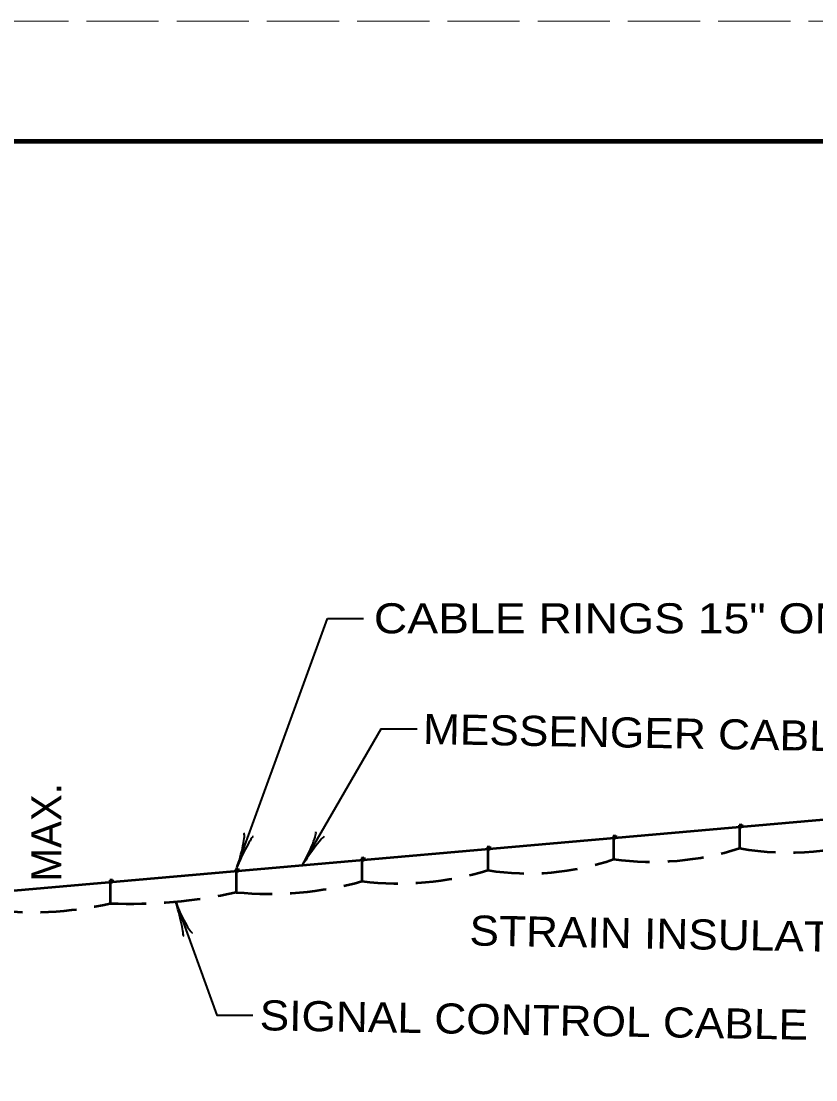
# Model space of a CAD drawing. Extents: x 12366 to 13046, y 9129 to 9570.
# Drawn here: x 12563.1 to 12629.1, y 9481.6 to 9569.5 of the extents above; entities that cross this region are included whole.
import ezdxf
from ezdxf.enums import TextEntityAlignment as Align

# ---------------------------------------------------------------- set-up
doc = ezdxf.new("R2010")
doc.units = 0
doc.linetypes.add('LONG_DASHED', pattern=[7.5, 6, -1.5])
doc.linetypes.add('MEDIUM_DASHED', pattern=[4.5, 3, -1.5])
doc.layers.add('1', color=7, linetype='Continuous', lineweight=53)
doc.layers.add('61', color=7, linetype='Continuous', lineweight=35)

msp = doc.modelspace()

# ---------------------------------------------------------------- linework, layer by layer
at = {"layer": '1', "lineweight": 35}
for p, q in [((12580.994, 9499.235), (12588.519, 9519.908)), ((12588.519, 9519.908), (12591.519, 9519.908))]:
    msp.add_line(p, q, dxfattribs=at)
at = {"layer": '1'}
for p, q in [((12632.351, 9503.418), (12561.823, 9497.248)), ((12622.748, 9502.779), (12622.947, 9502.796)), ((12622.748, 9502.779), (12622.765, 9502.579)), ((12622.752, 9502.729), (12622.901, 9502.742)), ((12622.752, 9502.729), (12622.765, 9502.579)), ((12622.761, 9502.78), (12622.779, 9502.581)), ((12622.765, 9502.73), (12622.779, 9502.581)), ((12622.765, 9502.579), (12622.964, 9502.597)), ((12622.765, 9502.579), (12622.914, 9502.593)), ((12622.765, 9502.579), (12622.765, 9500.829)), ((12622.776, 9502.781), (12622.794, 9502.582)), ((12622.781, 9502.731), (12622.794, 9502.582)), ((12622.791, 9502.783), (12622.809, 9502.583)), ((12622.796, 9502.733), (12622.809, 9502.583)), ((12622.806, 9502.784), (12622.824, 9502.585)), ((12622.811, 9502.734), (12622.824, 9502.585)), ((12622.814, 9502.785), (12622.832, 9502.585)), ((12622.825, 9502.786), (12622.842, 9502.586)), ((12622.829, 9502.736), (12622.842, 9502.586)), ((12622.836, 9502.787), (12622.854, 9502.587)), ((12622.841, 9502.737), (12622.854, 9502.587)), ((12622.847, 9502.788), (12622.864, 9502.588)), ((12622.855, 9502.788), (12622.873, 9502.589)), ((12622.86, 9502.738), (12622.873, 9502.589)), ((12622.87, 9502.789), (12622.888, 9502.59)), ((12622.875, 9502.74), (12622.888, 9502.59)), ((12622.885, 9502.791), (12622.903, 9502.592)), ((12622.89, 9502.741), (12622.903, 9502.592)), ((12622.897, 9502.792), (12622.914, 9502.593)), ((12622.901, 9502.742), (12622.914, 9502.593)), ((12622.908, 9502.793), (12622.925, 9502.593)), ((12622.918, 9502.794), (12622.935, 9502.594)), ((12622.928, 9502.794), (12622.945, 9502.595)), ((12622.938, 9502.795), (12622.955, 9502.596)), ((12622.947, 9502.796), (12622.964, 9502.597)), ((12612.288, 9501.864), (12612.487, 9501.881)), ((12612.288, 9501.864), (12612.305, 9501.664)), ((12612.301, 9501.865), (12612.318, 9501.666)), ((12612.305, 9501.664), (12612.454, 9501.677)), ((12612.305, 9501.664), (12612.305, 9499.914)), ((12612.316, 9501.866), (12612.334, 9501.667)), ((12612.331, 9501.868), (12612.349, 9501.668)), ((12612.346, 9501.869), (12612.364, 9501.669)), ((12612.354, 9501.869), (12612.372, 9501.67)), ((12612.365, 9501.87), (12612.382, 9501.671)), ((12612.376, 9501.871), (12612.394, 9501.672)), ((12612.387, 9501.872), (12612.404, 9501.673)), ((12612.395, 9501.873), (12612.413, 9501.674)), ((12612.41, 9501.874), (12612.428, 9501.675)), ((12612.425, 9501.876), (12612.443, 9501.676)), ((12612.437, 9501.877), (12612.454, 9501.677)), ((12612.448, 9501.878), (12612.465, 9501.678)), ((12612.458, 9501.878), (12612.475, 9501.679)), ((12612.468, 9501.879), (12612.485, 9501.68)), ((12612.477, 9501.88), (12612.495, 9501.681)), ((12612.487, 9501.881), (12612.504, 9501.682)), ((12601.827, 9500.949), (12602.027, 9500.966)), ((12601.827, 9500.949), (12601.845, 9500.749)), ((12601.832, 9500.899), (12601.981, 9500.912)), ((12601.832, 9500.899), (12601.845, 9500.749)), ((12601.841, 9500.95), (12601.858, 9500.751)), ((12601.845, 9500.9), (12601.858, 9500.751)), ((12601.856, 9500.951), (12601.873, 9500.752)), ((12601.86, 9500.901), (12601.873, 9500.752)), ((12601.871, 9500.952), (12601.889, 9500.753)), ((12601.876, 9500.902), (12601.889, 9500.753)), ((12601.886, 9500.954), (12601.904, 9500.754)), ((12601.891, 9500.904), (12601.904, 9500.754)), ((12601.894, 9500.954), (12601.912, 9500.755)), ((12601.905, 9500.955), (12601.922, 9500.756)), ((12601.909, 9500.905), (12601.922, 9500.756)), ((12601.916, 9500.956), (12601.933, 9500.757)), ((12601.92, 9500.906), (12601.933, 9500.757)), ((12601.927, 9500.957), (12601.944, 9500.758)), ((12601.935, 9500.958), (12601.953, 9500.759)), ((12601.94, 9500.908), (12601.953, 9500.759)), ((12601.95, 9500.959), (12601.968, 9500.76)), ((12601.955, 9500.909), (12601.968, 9500.76)), ((12601.965, 9500.96), (12601.983, 9500.761)), ((12601.969, 9500.911), (12601.983, 9500.761)), ((12601.977, 9500.961), (12601.994, 9500.762)), ((12601.981, 9500.912), (12601.994, 9500.762)), ((12601.988, 9500.962), (12602.005, 9500.763)), ((12601.997, 9500.963), (12602.015, 9500.764)), ((12602.007, 9500.964), (12602.025, 9500.765)), ((12602.017, 9500.965), (12602.035, 9500.766)), ((12602.027, 9500.966), (12602.044, 9500.767)), ((12591.367, 9500.033), (12591.567, 9500.051)), ((12591.367, 9500.033), (12591.385, 9499.834)), ((12591.372, 9499.984), (12591.521, 9499.996)), ((12591.372, 9499.984), (12591.385, 9499.834)), ((12591.381, 9500.034), (12591.398, 9499.835)), ((12591.385, 9499.985), (12591.398, 9499.835)), ((12591.396, 9500.036), (12591.413, 9499.837)), ((12591.4, 9499.986), (12591.413, 9499.837)), ((12591.411, 9500.037), (12591.428, 9499.838)), ((12591.415, 9499.987), (12591.428, 9499.838)), ((12591.426, 9500.038), (12591.444, 9499.839)), ((12591.431, 9499.989), (12591.444, 9499.839)), ((12591.434, 9500.039), (12591.451, 9499.84)), ((12591.445, 9500.04), (12591.462, 9499.841)), ((12591.449, 9499.99), (12591.462, 9499.841)), ((12591.456, 9500.041), (12591.473, 9499.842)), ((12591.46, 9499.991), (12591.473, 9499.842)), ((12591.467, 9500.042), (12591.484, 9499.843)), ((12591.475, 9500.043), (12591.493, 9499.844)), ((12591.479, 9499.993), (12591.493, 9499.844)), ((12591.49, 9500.044), (12591.508, 9499.845)), ((12591.494, 9499.994), (12591.508, 9499.845)), ((12591.505, 9500.045), (12591.522, 9499.846)), ((12591.509, 9499.995), (12591.522, 9499.846)), ((12591.517, 9500.046), (12591.534, 9499.847)), ((12591.521, 9499.996), (12591.534, 9499.847)), ((12591.528, 9500.047), (12591.545, 9499.848)), ((12591.537, 9500.048), (12591.555, 9499.849)), ((12591.547, 9500.049), (12591.565, 9499.85)), ((12591.557, 9500.05), (12591.575, 9499.851)), ((12591.567, 9500.051), (12591.584, 9499.851)), ((12601.845, 9500.749), (12602.044, 9500.767)), ((12601.845, 9500.749), (12601.994, 9500.762)), ((12601.845, 9500.749), (12601.845, 9498.999)), ((12580.91, 9499.119), (12581.11, 9499.137)), ((12580.91, 9499.119), (12580.928, 9498.92)), ((12580.915, 9499.069), (12581.064, 9499.083)), ((12580.915, 9499.069), (12580.928, 9498.92)), ((12580.924, 9499.12), (12580.941, 9498.921)), ((12580.928, 9499.071), (12580.941, 9498.921)), ((12580.939, 9499.122), (12580.957, 9498.923)), ((12580.943, 9499.072), (12580.957, 9498.923)), ((12580.954, 9499.123), (12580.972, 9498.924)), ((12580.959, 9499.073), (12580.972, 9498.924)), ((12580.969, 9499.124), (12580.987, 9498.925)), ((12580.974, 9499.075), (12580.987, 9498.925)), ((12580.977, 9499.125), (12580.994, 9498.926)), ((12580.988, 9499.126), (12581.005, 9498.927)), ((12580.992, 9499.076), (12581.005, 9498.927)), ((12580.999, 9499.127), (12581.016, 9498.928)), ((12581.003, 9499.077), (12581.016, 9498.928)), ((12581.01, 9499.128), (12581.027, 9498.929)), ((12581.018, 9499.129), (12581.036, 9498.93)), ((12581.023, 9499.079), (12581.036, 9498.93)), ((12581.033, 9499.13), (12581.051, 9498.931)), ((12581.038, 9499.08), (12581.051, 9498.931)), ((12581.048, 9499.131), (12581.065, 9498.932)), ((12581.052, 9499.082), (12581.065, 9498.932)), ((12581.06, 9499.132), (12581.077, 9498.933)), ((12581.064, 9499.083), (12581.077, 9498.933)), ((12581.071, 9499.133), (12581.088, 9498.934)), ((12581.08, 9499.134), (12581.098, 9498.935)), ((12581.091, 9499.135), (12581.108, 9498.936)), ((12581.1, 9499.136), (12581.118, 9498.937)), ((12581.11, 9499.137), (12581.127, 9498.937)), ((12591.385, 9499.834), (12591.584, 9499.851)), ((12591.385, 9499.834), (12591.534, 9499.847)), ((12591.385, 9499.834), (12591.385, 9498.084)), ((12570.447, 9498.203), (12570.646, 9498.22)), ((12570.447, 9498.203), (12570.465, 9498.004)), ((12570.452, 9498.153), (12570.601, 9498.166)), ((12570.452, 9498.153), (12570.465, 9498.004)), ((12570.461, 9498.204), (12570.478, 9498.005)), ((12570.465, 9498.154), (12570.478, 9498.005)), ((12570.476, 9498.206), (12570.493, 9498.006)), ((12570.48, 9498.156), (12570.493, 9498.006)), ((12570.491, 9498.207), (12570.508, 9498.007)), ((12570.495, 9498.157), (12570.508, 9498.007)), ((12570.506, 9498.208), (12570.523, 9498.009)), ((12570.51, 9498.158), (12570.523, 9498.009)), ((12570.514, 9498.209), (12570.531, 9498.01)), ((12570.524, 9498.21), (12570.542, 9498.011)), ((12570.529, 9498.16), (12570.542, 9498.011)), ((12570.536, 9498.211), (12570.553, 9498.012)), ((12570.54, 9498.161), (12570.553, 9498.012)), ((12570.547, 9498.212), (12570.564, 9498.012)), ((12570.555, 9498.212), (12570.572, 9498.013)), ((12570.559, 9498.163), (12570.572, 9498.013)), ((12570.57, 9498.214), (12570.587, 9498.014)), ((12570.574, 9498.164), (12570.587, 9498.014)), ((12570.585, 9498.215), (12570.602, 9498.016)), ((12570.589, 9498.165), (12570.602, 9498.016)), ((12570.597, 9498.216), (12570.614, 9498.017)), ((12570.601, 9498.166), (12570.614, 9498.017)), ((12570.608, 9498.217), (12570.625, 9498.018)), ((12570.617, 9498.218), (12570.635, 9498.019)), ((12570.627, 9498.219), (12570.645, 9498.019)), ((12570.637, 9498.219), (12570.654, 9498.02)), ((12570.646, 9498.22), (12570.664, 9498.021)), ((12580.928, 9498.92), (12581.127, 9498.937)), ((12580.928, 9498.92), (12581.077, 9498.933)), ((12580.928, 9498.92), (12580.928, 9497.17)), ((12570.465, 9498.004), (12570.664, 9498.021)), ((12570.465, 9498.004), (12570.614, 9498.017)), ((12570.465, 9498.004), (12570.465, 9496.254))]:
    msp.add_line(p, q, dxfattribs=at)
at = {"layer": '1', "lineweight": 35}
for points in [[(12586.48, 9499.496), (12592.98, 9510.755), (12595.98, 9510.755)], [(12575.912, 9496.37), (12579.332, 9486.973), (12582.332, 9486.973)]]:
    msp.add_lwpolyline(points, dxfattribs=at)
at = {"layer": '1', "linetype": 'MEDIUM_DASHED'}
for centre, radius, start, end in [((12626.841, 9524.298), 23.82, 260.14661, 289.87015), ((12615.487, 9523.782), 24.079, 262.4067, 287.5936), ((12605.216, 9520.707), 21.968, 261.17367, 288.82663), ((12594.419, 9523.642), 25.738, 263.23016, 286.77014), ((12583.655, 9526.241), 29.199, 264.64029, 285.35034), ((12572.139, 9537.33), 41.11, 267.66564, 282.34434), ((12563.981, 9524.338), 28.823, 262.41333, 283)]:
    msp.add_arc(centre, radius, start, end, dxfattribs=at)
at = {"layer": '1', "lineweight": 40}
for centre, major_axis, ratio, start_param, end_param in [((12581.108, 9500.354), (-0.464, -1.731), 0.122415, 0.896353, 3.141593), ((12581.576, 9500.215), (0.766, 1.59), 0.07063, 6.282307, 8.559703), ((12586.786, 9500.58), (-0.758, -1.625), 0.122415, 0.896353, 3.141593), ((12587.223, 9500.361), (1.03, 1.433), 0.07063, 6.282307, 8.559703), ((12576.096, 9495.245), (0.436, -1.711), 0.07063, 6.282307, 8.559703), ((12576.545, 9495.439), (-0.757, 1.625), 0.122415, 0.896353, 3.141593)]:
    msp.add_ellipse(centre, major_axis=major_axis, ratio=ratio, start_param=start_param, end_param=end_param, dxfattribs=at)
at = {"layer": '61', "linetype": 'LONG_DASHED', "lineweight": 13}
msp.add_line((12365.992, 9569.533), (13046.012, 9569.533), dxfattribs=at)
at = {"layer": '61', "lineweight": 158}
msp.add_lwpolyline([(13035.032, 9559.533), (12395.992, 9559.533), (12395.992, 9139.513)], dxfattribs=at)

# ---------------------------------------------------------------- texts
at = {"layer": '1', "width": 1.15}
msp.add_text('CABLE RINGS 15" ON CENTER', height=2.5, dxfattribs=at).set_placement((12592.377, 9518.681))
at = {"layer": '1', "width": 1.1}
for s, p in [('MESSENGER CABLE', (12596.444, 9509.494)), ('SIGNAL CONTROL CABLE', (12582.871, 9485.716))]:
    msp.add_text(s, height=2.5, rotation=359, dxfattribs=at).set_placement(p)
at = {"layer": '1'}
msp.add_text('MAX.', height=2.5, rotation=90, dxfattribs=at).set_placement((12566.406, 9502.156), align=Align.CENTER)
at = {"layer": '1', "width": 1.1}
msp.add_text('STRAIN INSULATOR', height=2.5, rotation=359, dxfattribs=at).set_placement((12635.852, 9492.139), align=Align.RIGHT)

doc.saveas('drawing.dxf')
